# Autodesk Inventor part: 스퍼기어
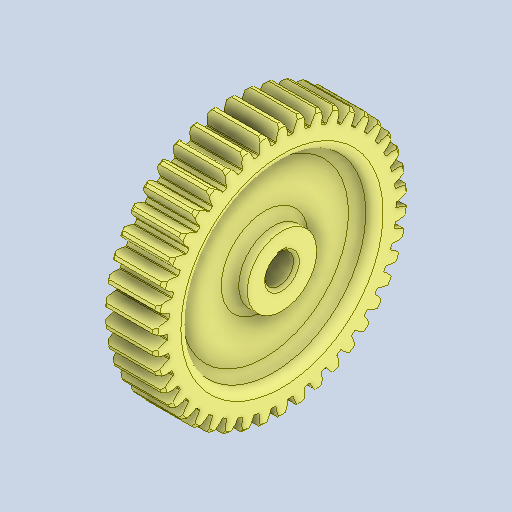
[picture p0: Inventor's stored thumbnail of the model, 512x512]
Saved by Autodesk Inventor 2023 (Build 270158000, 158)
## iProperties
Created: 2024-09
Part Number: 스퍼기어
Material: 강철, 탄소
Document SubType Name: Modeling
Designer: asung
Density: 7.85 g/cm^3
Appearance: 기본값
Author: jhkim
Sending System: Autodesk Inventor 2025
Preprocessor: ST-DEVELOPER v20
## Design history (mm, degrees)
feature "솔리드1"
node "솔리드2"
